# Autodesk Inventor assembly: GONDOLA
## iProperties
Shininess: 64.0
Length Units: 11272
Angle Units: 11279
Time Units: 11290
Mass Units: 11286
Length Display Precision: 3
Angle Display Precision: 2
Compacted: True
Part Number: GONDOLA
Document SubType Name: Assembly
Created: 2004-08
Designer: John Blackburn
Manufacturer: Standard
Standards Organization: Custom
Density: 0.0
Volumn: 0.0
Area: 0.0
PropertySet Name: Model Information
Control State: 0
Master: False
Checked Out: False
Author: John Blackburn
